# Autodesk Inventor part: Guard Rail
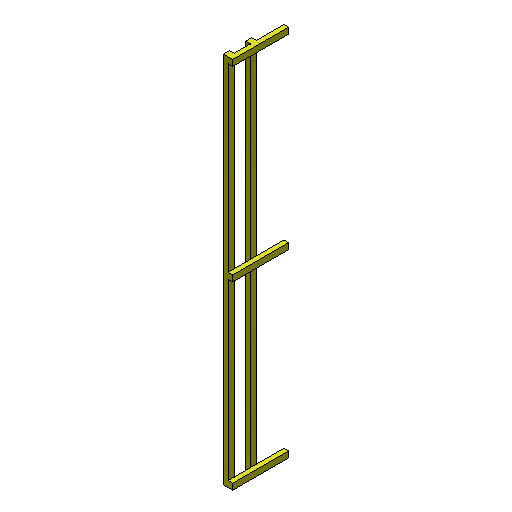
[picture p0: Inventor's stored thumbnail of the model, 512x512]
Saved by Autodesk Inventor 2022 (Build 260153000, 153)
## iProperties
Created: 2009-09
Part Number: Guard Rail
Document SubType Name: Modeling
Designer: Autodesk, Inc.
Density: 1 g/cm^3
Material: 一般
Appearance: 滑らか - 黄
ConnectorClass: SafetyEquipment
family_type: GuardRail
Key Parameters: Length=6101.100 mm;Height=914.400 mm;
Title: Guard Rail
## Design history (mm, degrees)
sketch "Sketch1"
  geometry: L1 (0, 0)-(-76.2, 0); L2 (-76.2, 0)-(-76.2, 99.1); L3 (-76.2, 99.1)-(0, 99.1); L4 (0, 99.1)-(0, 0)
  constraints: 8 end point, 2 parallel, 1 horizontal, 1 perpendicular
  dimensions: "d0" = 99.1 distance of L1.end L2.end (= PillarLength); "d1" = 76.2 distance of L1.start L1.end (= PillarWidth)
extrude "Extrusion1" new body sketch "Sketch1" distance "d2" = 914.4 (derived); taper "d3" = 0 deg
sketch "Sketch5"
  geometry: L1 (0, 0)-(-99.1, 0); L2 (-99.1, 0)-(-99.1, 6101.1); L3 (-99.1, 6101.1)-(0, 6101.1); L4 (0, 6101.1)-(0, 0)
  constraints: 8 end point, 2 parallel, 1 horizontal, 1 perpendicular
  dimensions: "d8" = 6101.1 distance of L3.end L1.start (derived); "d9" = 99.1 distance of L2.end L3.end (= PillarLength)
extrude "Extrusion2" join sketch "Sketch5" distance "d10" = 76.2 (= PillarWidth); taper "d11" = 0 deg
pattern_linear "Rectangular Pattern1" dims "d14" = 365.76 (= ArrayLevel)
pattern_linear "Rectangular Pattern2" dims "d17" = 2950
sketch "Sketch6"
  geometry: L1 (99.1, 6101.1)-(99.1, 3049.1) reference; L2 (0, 6101.1)-(99.1, 6101.1) reference; L3 (0, 99.1)-(0, 2950) reference; L4 (464.86, 6101.1)-(464.86, 3049.1) reference; L5 (365.76, 6101.1)-(464.86, 6101.1) reference; L6 (365.76, 99.1)-(365.76, 2950) reference; L7 (0, 6101.1)-(914.4, 6101.1); L8 (914.4, 6101.1)-(914.4, 6002); L9 (914.4, 6002)-(0, 6002); L10 (0, 6002)-(0, 6101.1); L11 (365.76, 99.1)-(464.86, 99.1) reference; L12 (0, 99.1)-(99.1, 99.1) reference; L13 (464.86, 2950)-(365.76, 2950) reference; L14 (464.86, 2950)-(464.86, 99.1) reference; L15 (365.76, 3049.1)-(464.86, 3049.1) reference; L16 (365.76, 3049.1)-(365.76, 6101.1) reference; L17 (99.1, 2950)-(0, 2950) reference; L18 (99.1, 2950)-(99.1, 99.1) reference; L19 (0, 3049.1)-(99.1, 3049.1) reference; L20 (0, 3049.1)-(0, 6101.1) reference; 1 further point
  constraints: 8 end point, 2 parallel, 1 horizontal, 1 perpendicular
  dimensions: "d18" = 99.1 distance of L9.end L2.start (= PillarLength); "d19" = 914.4 distance of L2.start L7.end (derived)
extrude "Extrusion3" join sketch "Sketch6" distance "d20" = 76.2 (= PillarWidth); taper "d21" = 0 deg
node "Connector_Work Plane1"
node "Connector_Work Plane2"
node "Connector_Work Plane3"
node "Connector_Work Plane4"
node "Connector_Work Plane5"
node "Connector_Work Axis1"
node "Connector1_Work Point1"
node "Connector2_Work Point1"
node "Landing Surface_Work Point1"
  workaxis "Work Axis7"
  workaxis "Work Axis8"
node "Landing Surface"
node "Insertion Point1"
node "Connector1"
node "Connector2"
body "Solid1"
node "Projected Loop1"
node "Projected Loop2"
workplane "Work Plane7"
other parameters: "TurnLength" = 1000.8 [user parameter], "PillarLength" = 99.1 [user parameter; used in 3 equation terms], "PillarWidth" = 76.2 [user parameter; used in 3 equation terms], "ArrayLevel" = 365.76 [user parameter; used in 2 equation terms], "d48" = -76.2, "d49" = 6101.1, "d50" = -464.86, "d51" = 0, "d52" = 0, "d53" = -90 deg, "d54" = -76.2, "d55" = 0, "d56" = -464.86, "d57" = 0, "d58" = 0, "d59" = 90 deg
